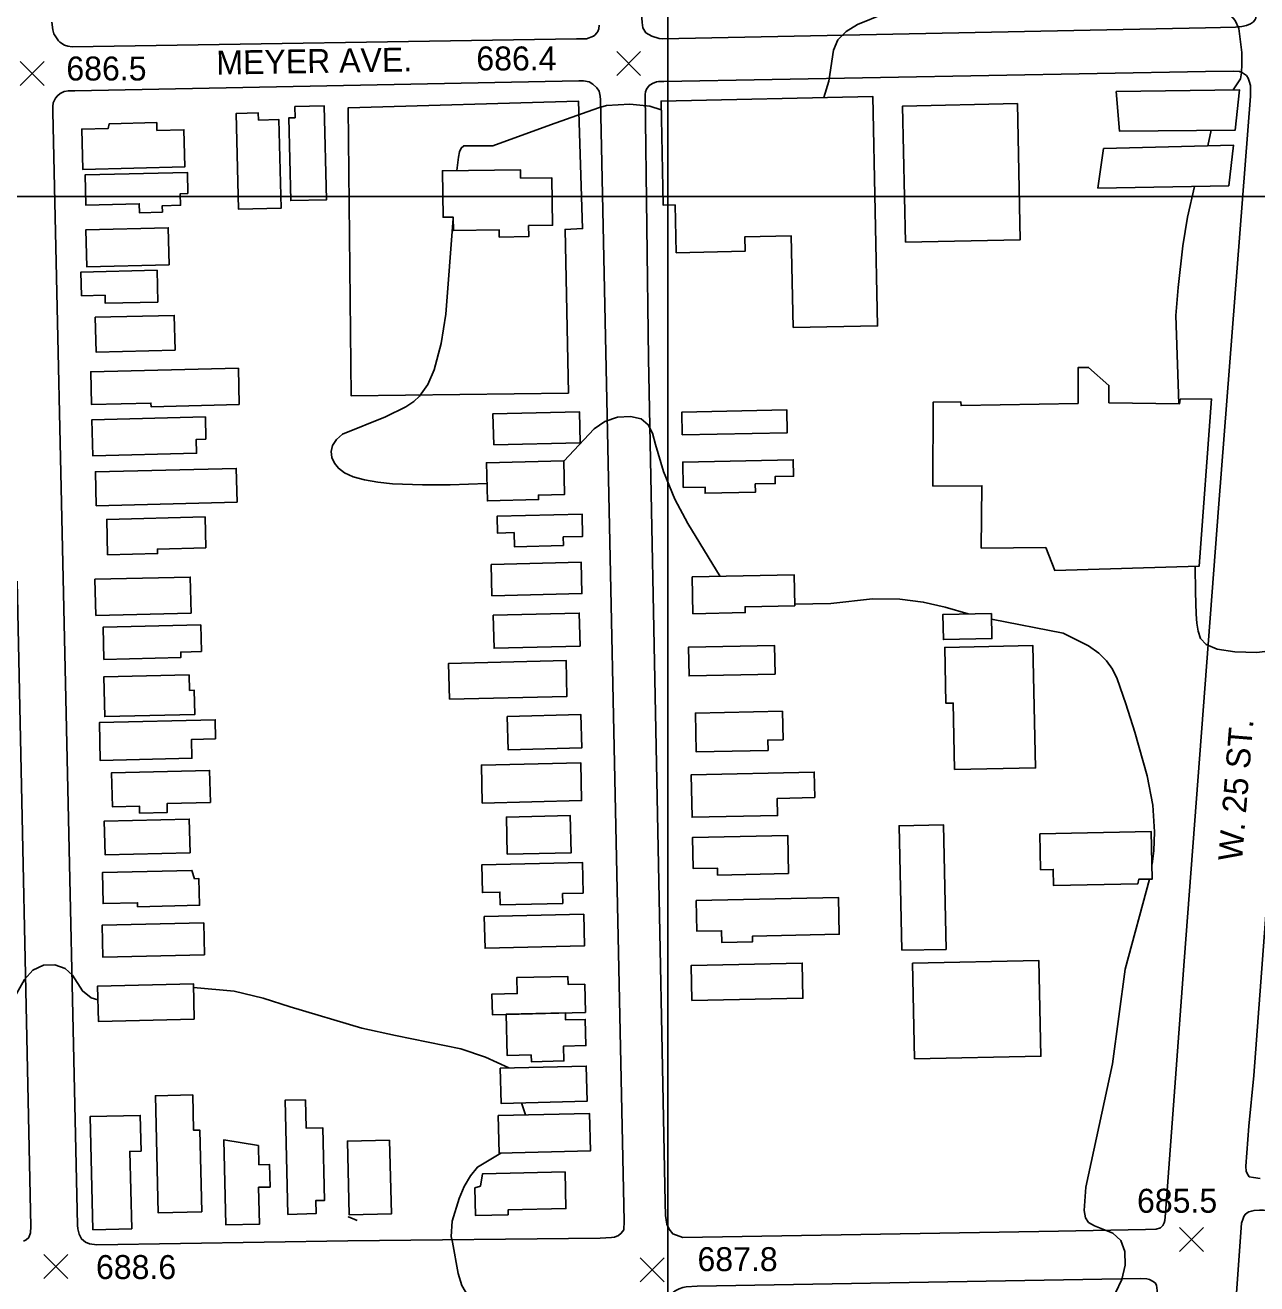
# Model space of a CAD drawing. Extents: x 79600 to 91800, y 75600 to 84400.
# Drawn here: x 83598 to 84369, y 76319 to 77107 of the extents above; entities that cross this region are included whole.
import ezdxf

# ---------------------------------------------------------------- set-up
doc = ezdxf.new("R2010")
doc.units = 0
for name, color, linetype in [('080-085$0$BLDG', 7, 'Continuous'), ('080-085$0$GRID', 7, 'Continuous'), ('080-085$0$INTER', 7, 'Continuous'), ('080-085$0$RECREATION', 7, 'Continuous'), ('080-085$0$ROAD', 7, 'Continuous'), ('080-085$0$ROAD-NAME', 7, 'Continuous'), ('080-085$0$SPOTMARK', 7, 'Continuous'), ('080-085$0$SPOTS', 7, 'Continuous')]:
    doc.layers.add(name, color=color, linetype=linetype)

# ---------------------------------------------------------------- blocks, each defined once
blk = doc.blocks.new('080-085$0$SPOTS')
at = {"layer": '080-085$0$SPOTMARK'}
for p, q in [((-0.5, -0.5), (0.5, 0.5)), ((-0.5, 0.5), (0.5, -0.5))]:
    blk.add_line(p, q, dxfattribs=at)

msp = doc.modelspace()

# ---------------------------------------------------------------- linework, layer by layer
at = {"layer": '080-085$0$BLDG'}
for points in [[(84280.82, 77065.57), (84357.85, 77066.76), (84355.26, 77041.51), (84282.86, 77040.73)], [(84078.48, 76917.84), (84077.29, 76975.21), (84048.25, 76974.61), (84048.44, 76965.58), (84005.27, 76964.67), (84004.64, 76994.59), (83997.22, 76994.44), (83995.86, 77059.66), (84128.42, 77062.43), (84131.41, 76918.94)], [(83743.74, 77047.78), (83743.63, 77052.24), (83729.82, 77051.9), (83731.28, 76991.9), (83757.93, 76992.55), (83756.58, 77048.09)], [(83766.56, 77056.16), (83766.73, 77049.18), (83762.7, 77049.09), (83763.96, 76997.32), (83786.38, 76997.87), (83784.94, 77056.61)], [(84148.84, 76971.29), (84147.06, 77056.54), (84218.88, 77058.04), (84220.66, 76972.79)], [(83680.22, 77041.28), (83680.1, 77046.19), (83650.32, 77045.46), (83649.69, 77042.5), (83633.14, 77042.09), (83633.76, 77016.86), (83697.63, 77018.42), (83697.07, 77041.69)], [(84272.87, 77029.96), (84354.25, 77031.97), (84351.23, 77006.59), (84269.29, 77005.13)], [(83699.61, 77001.73), (83694.84, 77001.62), (83695.01, 76994.4), (83683.51, 76994.12), (83683.6, 76990.12), (83669.24, 76989.77), (83669.1, 76995.32), (83635.66, 76994.51), (83635.2, 77013.44), (83699.29, 77015.01)], [(83907.78, 77011.31), (83927.48, 77011.58), (83927.9, 76981.87), (83912.86, 76981.66), (83912.95, 76974.78), (83894.55, 76974.53), (83894.49, 76978.99), (83865.77, 76978.59), (83865.65, 76987.02), (83859.36, 76986.93), (83858.96, 77016), (83907.71, 77016.67)], [(83687.82, 76957.09), (83636.35, 76955.83), (83635.78, 76979.12), (83687.25, 76980.38)], [(83680.77, 76933.85), (83647.81, 76933.04), (83647.68, 76938.11), (83632.97, 76937.75), (83632.61, 76952.57), (83680.29, 76953.73)], [(83691.53, 76903.67), (83642.13, 76902.46), (83641.6, 76924.29), (83690.99, 76925.5)], [(84340.34, 76873.33), (84332.75, 76768.54), (84242.24, 76765.84), (84236.67, 76780.17), (84196.26, 76779.86), (84196.65, 76818.87), (84166.06, 76818.67), (84166.07, 76871.15), (84183.47, 76871.38), (84183.6, 76868.99), (84256.85, 76870.33), (84257.05, 76892.92), (84263.5, 76892.9), (84276.24, 76881.64), (84276.21, 76870.84), (84320.4, 76870.15), (84320.83, 76873.1)], [(83731.71, 76869.6), (83676.49, 76868.25), (83676.43, 76870.63), (83639.22, 76869.73), (83638.72, 76890.17), (83731.16, 76892.43)], [(83710.91, 76847.95), (83704.78, 76847.8), (83704.99, 76839.16), (83640.05, 76837.57), (83639.5, 76860.16), (83710.57, 76861.9)], [(83891.06, 76844.45), (83890.59, 76863.88), (83944.67, 76865.2), (83945.15, 76845.77)], [(84009.12, 76850.68), (84074.84, 76852.05), (84074.54, 76866.37), (84008.82, 76865)], [(83730.39, 76808.46), (83642.16, 76806.31), (83641.64, 76827.57), (83729.87, 76829.72)], [(83934.88, 76834.42), (83886.51, 76833.24), (83887.09, 76809.35), (83919.08, 76810.13), (83919.01, 76813.02), (83935.39, 76813.42)], [(84009.67, 76817.69), (84023.32, 76817.97), (84023.4, 76814.14), (84054.92, 76814.8), (84054.82, 76819.95), (84067.28, 76820.21), (84067.19, 76824.54), (84078.83, 76824.78), (84078.61, 76835.15), (84009.34, 76833.7)], [(83710.85, 76779.95), (83680.53, 76779.21), (83680.6, 76776.4), (83649.29, 76775.63), (83648.75, 76797.81), (83710.38, 76799.32)], [(83903.77, 76789.51), (83893.36, 76789.25), (83893.1, 76799.77), (83946.33, 76801.07), (83946.67, 76787.11), (83934.55, 76786.81), (83934.68, 76781.43), (83903.99, 76780.68)], [(83889.47, 76769.64), (83945.77, 76771.01), (83946.25, 76751.37), (83889.95, 76750)], [(83701.59, 76739.15), (83641.96, 76737.69), (83641.41, 76760.26), (83701.04, 76761.71)], [(84079.65, 76743.73), (84048.45, 76743.08), (84048.52, 76739.41), (84015.78, 76738.73), (84015.3, 76761.73), (84079.24, 76763.06)], [(83890.76, 76737.84), (83944.61, 76739.15), (83945.11, 76718.48), (83891.26, 76717.16)], [(84202.62, 76738.96), (84172.3, 76738.33), (84172.63, 76722.51), (84202.95, 76723.14)], [(83708.04, 76715.03), (83695.13, 76714.71), (83695.21, 76711.35), (83647.01, 76710.17), (83646.52, 76730.22), (83707.64, 76731.71)], [(84067.17, 76700.89), (84013.39, 76699.77), (84013.01, 76717.79), (84066.79, 76718.91)], [(84179.6, 76641.17), (84178.73, 76682.81), (84174.17, 76682.72), (84173.44, 76717.6), (84228.66, 76718.75), (84230.26, 76642.23)], [(83863.36, 76685.18), (83936.87, 76686.97), (83936.32, 76709.46), (83862.81, 76707.66)], [(83700.59, 76690.71), (83703.6, 76690.78), (83703.97, 76675.66), (83647.51, 76674.29), (83646.9, 76699.12), (83700.35, 76700.43)], [(83716.94, 76660.32), (83701.82, 76659.95), (83702.11, 76648.25), (83644.73, 76646.84), (83644.15, 76670.56), (83716.65, 76672.33)], [(83899.49, 76674.41), (83945.67, 76675.54), (83946.17, 76654.71), (83900, 76653.59)], [(84072.18, 76659.8), (84062.64, 76659.6), (84062.77, 76653.16), (84017.87, 76652.22), (84017.37, 76676.51), (84071.8, 76677.65)], [(83713.65, 76620.57), (83686.56, 76619.91), (83686.7, 76614.35), (83669.29, 76613.93), (83669.18, 76618.32), (83652.36, 76617.91), (83651.84, 76639.14), (83713.16, 76640.64)], [(83883.88, 76620.22), (83883.3, 76643.94), (83945.49, 76645.45), (83946.06, 76621.74)], [(84092.07, 76623.58), (84068.58, 76623.09), (84068.8, 76612.41), (84015.27, 76611.3), (84014.71, 76637.93), (84091.74, 76639.54)], [(83700.95, 76589.13), (83647.76, 76587.83), (83647.24, 76608.9), (83700.44, 76610.19)], [(83899.56, 76588.15), (83898.99, 76611.42), (83938.98, 76612.4), (83939.55, 76589.12)], [(84146.45, 76528.03), (84144.82, 76606.03), (84172.62, 76606.61), (84174.25, 76528.61)], [(84233.43, 76578.47), (84241.39, 76578.64), (84241.6, 76568.58), (84294.36, 76569.68), (84294.87, 76572.46), (84303.37, 76572.64), (84302.75, 76602.32), (84232.96, 76600.86)], [(84075.67, 76576.02), (84031.16, 76575.09), (84031.06, 76579.51), (84015.98, 76579.2), (84015.58, 76598.66), (84075.17, 76599.9)], [(83703.64, 76572.8), (83706.5, 76572.87), (83706.91, 76556.2), (83668.11, 76555.25), (83668.05, 76557.84), (83646.52, 76557.31), (83646.05, 76576.71), (83702.1, 76578.08)], [(83934.12, 76563.51), (83934.26, 76557.4), (83895.1, 76556.45), (83894.91, 76564.46), (83883.98, 76564.2), (83883.56, 76581.5), (83946.56, 76583.04), (83947.03, 76563.82)], [(84017.86, 76559.23), (84018.26, 76539.98), (84033.66, 76540.3), (84033.81, 76532.94), (84053.14, 76533.34), (84053.06, 76536.9), (84107.32, 76538.03), (84106.84, 76561.09)], [(83947.36, 76550.67), (83885.1, 76549.15), (83885.59, 76529.28), (83947.85, 76530.8)], [(83709.94, 76525.26), (83646.37, 76523.71), (83645.89, 76543.66), (83709.45, 76545.21)], [(84015.16, 76496.61), (84084.63, 76498.06), (84084.17, 76520.03), (84014.7, 76518.58)], [(84153.15, 76519.96), (84232.38, 76521.61), (84233.63, 76461.74), (84154.4, 76460.09)], [(83703.53, 76484.96), (83643.56, 76483.49), (83643.02, 76505.63), (83702.99, 76507.09)], [(83948.04, 76506.9), (83937.56, 76506.64), (83937.44, 76511.7), (83905.5, 76510.92), (83905.74, 76500.97), (83889.91, 76500.58), (83890.23, 76487.71), (83948.47, 76489.13)], [(83914.5, 76462.5), (83914.6, 76458.3), (83935.01, 76458.8), (83934.78, 76468.08), (83948.75, 76468.42), (83948.35, 76484.75), (83936.06, 76484.45), (83935.95, 76488.89), (83898.85, 76487.98), (83899.48, 76462.13)], [(83895.07, 76454.25), (83948.97, 76455.57), (83949.51, 76433.5), (83895.61, 76432.18)], [(83702.6, 76437.53), (83703.14, 76415.33), (83706.99, 76415.43), (83708.23, 76364.34), (83681.05, 76363.67), (83679.26, 76436.96)], [(83773.16, 76434.52), (83773.59, 76416.74), (83784.02, 76416.99), (83785.13, 76371.46), (83779.63, 76371.33), (83779.83, 76363.17), (83762.22, 76362.74), (83760.48, 76434.21)], [(83670.28, 76402.25), (83663.2, 76402.08), (83664.38, 76353.68), (83640.07, 76353.09), (83638.34, 76423.89), (83669.73, 76424.66)], [(83893.78, 76424.53), (83950.96, 76425.92), (83951.54, 76402.44), (83894.36, 76401.05)], [(83743.69, 76405.93), (83743.99, 76393.75), (83750.72, 76393.91), (83751.06, 76379.85), (83743.79, 76379.68), (83744.35, 76356.58), (83723.42, 76356.07), (83722.11, 76409.38)], [(83825.87, 76409.23), (83827, 76363.01), (83800.57, 76362.37), (83799.44, 76408.59)], [(83882.68, 76380.45), (83879.29, 76379.33), (83879.72, 76361.94), (83900.07, 76362.44), (83899.99, 76365.46), (83936.25, 76366.34), (83935.69, 76389.28), (83883.97, 76388.02)]]:
    msp.add_lwpolyline(points, close=True, dxfattribs=at)
at = {"layer": '080-085$0$GRID'}
for p, q in [((84000, 80000), (84000, 76000)), ((85000, 77000), (80000, 77000))]:
    msp.add_line(p, q, dxfattribs=at)
at = {"layer": '080-085$0$INTER'}
for p, q in [((84340.21, 77041.35), (84338.06, 77031.57)), ((83910.95, 76424.94), (83908.34, 76432.49))]:
    msp.add_line(p, q, dxfattribs=at)
for points in [[(84097.71, 77061.79), (84100.93, 77072.15), (84103.8, 77091.51), (84106.54, 77097.92), (84111.67, 77103.28), (84118.69, 77107.65), (84135.26, 77114.17), (84153.02, 77118.4), (84181.23, 77121.67), (84253.61, 77125.5)], [(84348.78, 77116.28), (84352.62, 77113.13), (84355.2, 77110.08), (84357.47, 77105.12), (84359.44, 77090.02), (84359.46, 77082.69), (84359.14, 77077.24), (84358.53, 77073.51), (84354.07, 77066.7)], [(83868.05, 77016.12), (83868.92, 77024.57), (83869.59, 77027.83), (83870.61, 77030.22), (83872.32, 77031.63), (83890.44, 77031.53), (83926.61, 77044.76), (83956.74, 77055.5), (83961.62, 77056.88), (83976.23, 77057.74), (83988.7, 77056.53), (83995.97, 77054.15)], [(84329.85, 77006.21), (84325.45, 76986.9), (84322.47, 76969.02), (84319.59, 76942.87), (84318.19, 76925.36), (84320.02, 76870.16)], [(83886.82, 76820.31), (83863.75, 76819.46), (83846.52, 76819.34), (83827.67, 76820.06), (83818.5, 76821.03), (83810.11, 76822.49), (83803.04, 76824.44), (83797.68, 76826.88), (83793.85, 76829.77), (83791.28, 76833.03), (83789.72, 76836.61), (83789.3, 76840.35), (83790.21, 76844.12), (83792.58, 76847.78), (83796.45, 76851.2), (83823.38, 76862.07), (83836.09, 76868.17), (83840.94, 76871.49), (83844.68, 76874.87), (83849.85, 76882.31), (83853.73, 76891.45), (83858.07, 76907.97), (83860.96, 76926.34), (83865.66, 76986.06)], [(84032.86, 76762.1), (84012.66, 76795.23), (84004.4, 76810.45), (83997.41, 76827.77), (83992.41, 76844.72), (83990.41, 76851.65), (83987.75, 76857.04), (83983.36, 76860.64), (83976.59, 76862.22), (83968.49, 76861.7), (83960.52, 76859.07), (83953.85, 76854.5), (83934.88, 76834.13)], [(84330.29, 76768.47), (84330.31, 76752.14), (84330.72, 76738.51), (84331.24, 76732.82), (84332.1, 76727.77), (84333.63, 76723.26), (84337.08, 76719.45), (84343.95, 76716.57), (84355.07, 76714.83), (84368.71, 76714.55), (84382.47, 76716.05), (84394.45, 76719.49), (84404.74, 76724.33), (84422.38, 76735.49), (84436.33, 76745.2), (84444.65, 76751.39), (84446.88, 76753.72), (84448.01, 76756.07), (84448, 76758.87), (84430.18, 76793.18)], [(84188.05, 76738.66), (84173.74, 76742.86), (84159.93, 76746.04), (84145.21, 76747.82), (84128.23, 76748.03), (84102.02, 76745.16), (84079.63, 76744.67)], [(84303.18, 76581.86), (84304.38, 76590.24), (84304.83, 76602.29), (84303.66, 76618.81), (84300.18, 76637.22), (84292.33, 76664.68), (84286.81, 76682.35), (84281.36, 76697.99), (84278.38, 76704.1), (84274.72, 76709.3), (84269.88, 76714.06), (84263.49, 76718.69), (84247.62, 76726.46), (84202.7, 76735.32)], [(84280.36, 76313.63), (84284.38, 76321.96), (84286.43, 76330.88), (84286.26, 76339.39), (84283.65, 76346.32), (84278.71, 76350.86), (84267.21, 76355.54), (84263.48, 76357.61), (84261.44, 76360.56), (84260.69, 76365.12), (84261.73, 76379.7), (84278.4, 76456.99), (84286.34, 76516.3), (84301.58, 76572.6)], [(83643.23, 76497.1), (83639.1, 76498.17), (83633.66, 76502.64), (83627.41, 76512.42), (83622.73, 76516.72), (83616.36, 76518.95), (83609.21, 76518.64), (83602.51, 76515.58), (83597.21, 76509.82), (83589.6, 76495.9), (83586.21, 76490.71), (83582.27, 76487.09), (83577.06, 76484.64), (83570.12, 76483.05), (83561.85, 76482.35), (83552.84, 76482.64), (83520.62, 76489.8)], [(83900.42, 76454.39), (83885.93, 76461.19), (83870.51, 76466.38), (83829.56, 76474.62), (83808.37, 76479.32), (83763.7, 76492.7), (83746.76, 76498.06), (83728.48, 76502.35), (83703.05, 76504.76)], [(83884.89, 76303.76), (83878.8, 76308.18), (83874.72, 76312.24), (83871.07, 76318.09), (83868.69, 76325.69), (83865.25, 76345.34), (83864.46, 76348.88), (83865.08, 76358.41), (83869.35, 76372.75), (83872.63, 76380.12), (83876.52, 76386.82), (83880.88, 76392.3), (83895.58, 76401.08)], [(83805.45, 76358.84), (83800.03, 76361.16), (83805.45, 76358.84)]]:
    msp.add_lwpolyline(points, dxfattribs=at)
at = {"layer": '080-085$0$RECREATION'}
msp.add_lwpolyline([(83937.95, 76876.84), (83801.85, 76875.11), (83799.97, 77055.41), (83944.21, 77059.5), (83946.65, 76979.8), (83935.71, 76979.27)], close=True, dxfattribs=at)
at = {"layer": '080-085$0$ROAD'}
for points in [[(84336.62, 77105.51), (83996.79, 77098.5), (83994.69, 77098.78), (83990.07, 77100.2), (83986.28, 77102.45), (83984.47, 77105.4), (83983.92, 77108.77), (83983.65, 77114.39), (83968.08, 77819.89), (83968.1, 77824.8), (83968.24, 77826.2), (83969.23, 77828.45), (83969.79, 77829.43), (83970.92, 77830.69), (83972.89, 77832.22), (83975.14, 77833.2), (83978.08, 77834.03), (83992.82, 77834.97), (84336.62, 77840.64)], [(84336.62, 77840.64), (84411.8, 77841.98), (84415.95, 77841.37), (84418.15, 77840.5), (84422.4, 77837.53), (84423.03, 77833.92), (84422.97, 77830.04), (84368.84, 77118.52), (84368.64, 77114.79), (84368.18, 77111.61), (84367.75, 77110.79), (84366.62, 77109.28), (84364.79, 77107.92), (84362.29, 77106.99), (84359.51, 77106.34), (84355.49, 77105.99), (84336.62, 77105.51)], [(83956.97, 77107.17), (83956.83, 77104.92), (83956.26, 77103.24), (83955.56, 77102.26), (83954.43, 77101), (83953.59, 77100.3), (83949.09, 77098.63), (83942.92, 77098.51), (83627.07, 77093.49), (83624.41, 77093.92), (83622.31, 77094.63), (83619.37, 77096.46), (83618.53, 77097.45), (83617.27, 77099.13), (83615.73, 77101.8), (83615.04, 77104.33), (83614.35, 77108.96)], [(84244.62, 76352.28), (84009.43, 76348.24), (84003.12, 76350.51), (84000.89, 76353.46), (83999.49, 76356.55), (83998.53, 76362.02), (83998.41, 76370.16), (83987.96, 76898.58), (83985.89, 77063.73), (83986.04, 77065.41), (83986.75, 77067.09), (83988.44, 77069.33), (83990.4, 77070.73), (83992.93, 77071.71), (83994.34, 77071.98), (83997.56, 77071.98), (84336.62, 77078.11)], [(84336.62, 77078.11), (84353.96, 77078.45), (84357.97, 77078.12), (84359.89, 77077.26), (84362.36, 77075.56), (84363.44, 77073.88), (84364.1, 77072.07), (84364.89, 77069.29), (84364.93, 77062.78), (84344.95, 76807.58), (84323.37, 76521.12), (84311.54, 76363.43), (84311.19, 76358.87), (84310.89, 76357.35), (84310.03, 76355.7), (84308.49, 76354.34), (84305.84, 76353.55), (84299.19, 76353.24), (84244.62, 76352.28)], [(84370.86, 76385.23), (84366.72, 76385.71), (84364.09, 76386.17), (84363.28, 76387.29), (84362.07, 76389.52), (84361.84, 76392.99), (84363.89, 76418.02), (84366.87, 76449.69), (84390.91, 76770.87)], [(83592.61, 76759.1), (83601.16, 76355.14), (83601.01, 76351.07), (83600.02, 76348.26), (83598.33, 76346.87), (83596.64, 76345.89)], [(84351.83, 76255.08), (84359.22, 76357.3), (84360.23, 76360.19), (84360.66, 76361.29), (84361.51, 76362.67), (84362.78, 76363.75), (84363.89, 76364.29), (84365.43, 76364.82), (84367.09, 76365.21), (84370.42, 76365.3), (84373.05, 76365.26), (84392.15, 76364.55), (84547.9, 76353.29), (84568.1, 76351.74), (84577.22, 76350.35), (84585.65, 76349.25), (84601.12, 76346.52), (84641.71, 76338.42), (84779.62, 76310.54)], [(84007.1, 76000), (84000.76, 76308.84), (84001.19, 76311.37), (84002.32, 76312.91), (84004.71, 76314.86), (84007.1, 76316.12), (84009.34, 76316.95), (84011.59, 76317.37), (84018.33, 76317.77), (84296, 76322.47), (84299.93, 76322.32), (84301.62, 76321.89), (84303.44, 76320.9), (84305.12, 76319.78), (84305.95, 76318.37), (84306.51, 76315.14), (84306.49, 76310.65), (84306.06, 76306.3), (84282.98, 76000)]]:
    msp.add_lwpolyline(points, dxfattribs=at)
msp.add_lwpolyline([(83799.67, 76346.16), (83642.66, 76343.66), (83637.89, 76344.23), (83635.51, 76345.22), (83632.99, 76347.33), (83631.45, 76350.42), (83630.76, 76353.65), (83630.49, 76355.9), (83615.03, 77052.98), (83615.04, 77056.21), (83615.19, 77058.45), (83616.6, 77061.53), (83617.87, 77062.93), (83619.7, 77064.47), (83622.09, 77065.59), (83624.75, 77066.14), (83628.82, 77066.13), (83944.39, 77072.4), (83947.19, 77072.26), (83950.84, 77071.68), (83953.08, 77070.28), (83955.6, 77068.02), (83957, 77065.92), (83957.69, 77062.69), (83957.82, 77060.44), (83972.7, 76358.45), (83972.54, 76353.12), (83970.85, 76350.88), (83969.17, 76349.48), (83966.64, 76348.5), (83964.81, 76348.23), (83957.66, 76347.83)], close=True, dxfattribs=at)

# ---------------------------------------------------------------- block references
at = {"layer": '080-085$0$SPOTMARK', "xscale": 15, "yscale": 15}
for p in [(83975.52, 77083.2), (83602.14, 77076.91), (84327.93, 76346.92), (83616.82, 76330.14), (83990.21, 76328.04)]:
    msp.add_blockref('080-085$0$SPOTS', p, dxfattribs=at)

# ---------------------------------------------------------------- texts
at = {"layer": '080-085$0$ROAD-NAME'}
for s, rotation, p in [('MEYER AVE.', 0.96665, (83717.51, 77076.15)), ('W. 25 ST.', 85.33365, (84359.52, 76583.46))]:
    msp.add_text(s, height=15, rotation=rotation, dxfattribs=at).set_placement(p)
at = {"layer": '080-085$0$SPOTS'}
for s, p in [('686.4', (83880.17, 77078.82)), ('686.5', (83623.49, 77072.52)), ('685.5', (84293.81, 76363.74)), ('687.8', (84018.61, 76327.18)), ('688.6', (83642.04, 76322.23))]:
    msp.add_text(s, height=15, dxfattribs=at).set_placement(p)

doc.saveas('drawing.dxf')
